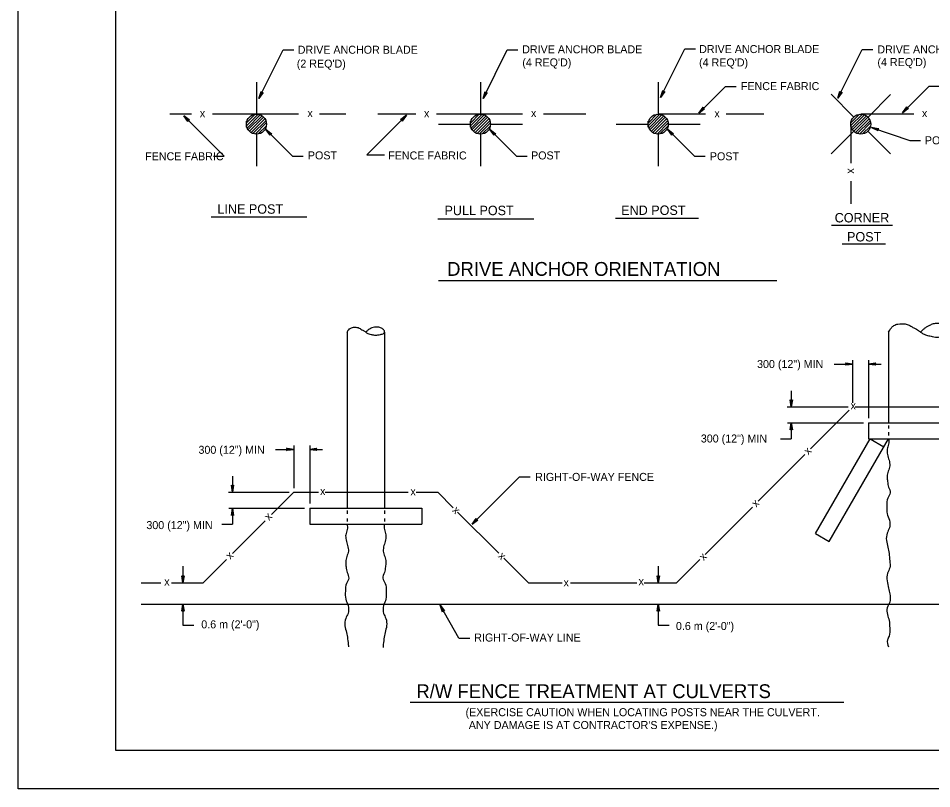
# Model space of a CAD drawing. Extents: x 13 to 918, y -903 to 879.
# Drawn here: x 13.3 to 370, y -903.1 to -602.3 of the extents above; entities that cross this region are included whole.
import ezdxf

# ---------------------------------------------------------------- set-up
doc = ezdxf.new("R2010")
doc.units = 0
for name, color, linetype in [('1', 7, 'Continuous'), ('2', 7, 'Continuous'), ('3', 7, 'Continuous'), ('PLT-BNDY', 7, 'Continuous')]:
    doc.layers.add(name, color=color, linetype=linetype)

msp = doc.modelspace()

# ---------------------------------------------------------------- linework, layer by layer
at = {"layer": '1'}
for p, q in [((80.93625, -639.7385), (72.47375, -639.7385)), ((122.69875, -639.7385), (89.157, -639.7385)), ((141.22375, -639.7385), (130.9195, -639.7385)), ((168.5155, -639.7385), (153.72375, -639.7385)), ((210.128, -639.7385), (176.607, -639.7385)), ((234.97375, -639.7385), (218.35075, -639.7385)), ((281.65775, -639.7385), (263.19525, -639.7385)), ((304.387, -639.7385), (289.73075, -639.7385)), ((363.04575, -639.7385), (342.29775, -639.7385)), ((338.3895, -643.64675), (338.3895, -658.876)), ((338.3895, -665.92175), (338.3895, -674.79675)), ((141.692, -724.81825), (141.692, -793.56825)), ((156.27525, -724.81825), (156.27525, -793.56825)), ((353.15025, -724.81825), (353.15025, -760.235)), ((331.91075, -737.27875), (339.117, -737.27875)), ((339.117, -735.79525), (339.117, -752.4265)), ((345.367, -735.79525), (345.367, -758.40575)), ((345.367, -737.27875), (350.296, -737.27875)), ((315.1795, -747.7745), (315.1795, -753.985)), ((313.617, -753.985), (337.367, -753.985)), ((313.692, -760.235), (343.346, -760.235)), ((315.1795, -760.235), (315.1795, -766.4225)), ((345.367, -760.235), (345.367, -766.485)), ((353.15025, -761.24375), (353.15025, -762.455)), ((310.96275, -766.4225), (315.1795, -766.4225)), ((353.15025, -763.828), (353.15025, -765.20075)), ((113.65225, -770.612), (120.8585, -770.612)), ((120.8585, -769.12875), (120.8585, -785.76)), ((127.1085, -769.12875), (127.1085, -791.739)), ((127.1085, -770.612), (132.03775, -770.612)), ((96.921, -781.10775), (96.921, -787.31825)), ((208.969, -781.38275), (213.18575, -781.38275)), ((95.3585, -787.31825), (119.1085, -787.31825)), ((95.4335, -793.56825), (125.08775, -793.56825)), ((96.921, -793.56825), (96.921, -799.75575)), ((127.1085, -793.56825), (127.1085, -799.81825)), ((141.692, -794.51675), (141.692, -795.72825)), ((156.27525, -794.436), (156.27525, -795.809)), ((170.8585, -793.56825), (170.8585, -799.81825)), ((141.692, -797.58575), (141.692, -798.71625)), ((156.27525, -797.58575), (156.27525, -798.797)), ((92.7045, -799.75575), (96.921, -799.75575)), ((77.542, -816.25575), (77.542, -822.735)), ((263.2335, -816.25575), (263.2335, -822.735)), ((77.542, -831.037), (77.542, -839.24125)), ((263.2335, -831.037), (263.2335, -839.24125)), ((77.542, -839.24125), (81.7585, -839.24125)), ((263.2335, -839.24125), (267.45025, -839.24125)), ((185.37525, -844.24125), (189.592, -844.24125))]:
    msp.add_line(p, q, dxfattribs=at)
msp.add_lwpolyline([(837.2505, -888.06975), (837.2505, -324.06975), (51.2505, -324.06975), (51.2505, -888.06975), (837.2505, -888.06975), (837.2505, -861.71075), (637.2505, -861.71075), (637.2505, -797.03325), (837.2505, -797.03325), (837.2505, -768.06975), (637.2505, -768.06975), (637.2505, -888.06975), (716.052, -888.06975), (716.052, -861.71075), (716.052, -888.06975), (793.052, -888.06975), (793.052, -861.71075), (793.052, -874.02725), (837.2505, -874.02725)], dxfattribs=at)
at = {"layer": '2'}
for points in [[(141.6565, -724.85775), (141.994, -724.3725), (142.3045, -723.887), (142.90025, -723.36), (143.8045, -723.0225), (145.4795, -722.99325), (146.39825, -723.264), (147.06075, -723.6975), (147.77525, -724.062), (148.27525, -724.36), (148.7065, -724.6015), (148.97725, -724.85775), (149.546, -725.237), (150.12525, -725.46625), (151.08575, -725.7515), (151.66475, -725.887), (152.367, -725.99325), (152.8795, -725.99325), (153.744, -725.9265), (154.67725, -725.7515), (155.33975, -725.6015), (156.02725, -725.264), (156.31075, -724.85775), (156.271, -724.33075), (155.85225, -723.84525), (155.35225, -723.44125), (154.78575, -723.17025), (154.01475, -722.95375), (153.09825, -722.887), (152.33975, -722.914), (151.394, -723.15775), (150.719, -723.50775), (150.08575, -723.84525), (149.5835, -724.264), (148.97725, -724.85775)], [(353.1545, -724.82025), (353.71075, -724.012), (354.244, -723.1725), (355.27325, -722.25575), (356.8045, -721.68075), (359.667, -721.64525), (361.2315, -722.10375), (362.37525, -722.82875), (363.59825, -723.47875), (364.442, -723.9725), (365.16475, -724.3975), (365.66075, -724.82025), (366.619, -725.462), (367.6085, -725.8475), (369.25225, -726.34525), (370.244, -726.5745), (371.4295, -726.76625), (372.3045, -726.76625), (373.796, -726.6475), (375.36475, -726.34525), (376.51075, -726.07875), (377.694, -725.5015), (378.169, -724.82025), (378.11075, -723.937), (377.38575, -723.09525), (376.546, -722.40575), (375.5545, -721.9475), (374.2545, -721.56825), (372.68975, -721.4515), (371.38975, -721.49525), (369.78575, -721.91), (368.60225, -722.5225), (367.5335, -723.09525), (366.692, -723.82025), (365.66075, -724.82025)]]:
    msp.add_spline(points, degree=3, dxfattribs=at)
at = {"layer": '3'}
for p, q in [((107.23625, -633.64675), (116.71325, -614.58025)), ((116.71325, -614.58025), (120.88, -614.58025)), ((194.778, -633.64675), (204.255, -614.58025)), ((204.255, -614.58025), (208.42175, -614.58025)), ((264.1015, -633.253), (273.57875, -614.1865)), ((273.57875, -614.1865), (277.74525, -614.1865)), ((333.3415, -633.5155), (342.81875, -614.449)), ((342.81875, -614.449), (346.98525, -614.449)), ((106.282, -627.2385), (106.282, -639.7385)), ((193.782, -627.2385), (193.782, -639.7385)), ((263.19525, -627.2385), (263.19525, -639.7385)), ((279.035, -639.3405), (289.4515, -628.924)), ((289.4515, -628.924), (293.61825, -628.924)), ((358.61025, -639.20925), (369.027, -628.79275)), ((369.027, -628.79275), (373.19375, -628.79275)), ((330.68525, -632.00525), (339.525, -640.84475)), ((345.13325, -640.924), (353.97275, -632.08425)), ((77.87175, -640.376), (93.6425, -656.14675)), ((102.4425, -643.12175), (105.753, -639.8115)), ((102.4675, -644.20525), (106.91125, -639.7615)), ((102.72575, -645.051), (107.728, -640.049)), ((103.08825, -645.79675), (108.45925, -640.426)), ((103.5945, -646.39475), (109.0405, -640.949)), ((104.22375, -646.874), (109.55075, -641.54675)), ((149.4155, -655.6135), (164.83625, -640.19275)), ((189.9425, -643.12175), (193.253, -639.8115)), ((189.9675, -644.20525), (194.41125, -639.7615)), ((190.22575, -645.051), (195.228, -640.049)), ((190.58825, -645.79675), (195.95925, -640.426)), ((191.0945, -646.39475), (196.5405, -640.949)), ((191.72375, -646.874), (197.05075, -641.54675)), ((259.35575, -643.12175), (262.66625, -639.8115)), ((259.38075, -644.20525), (263.8245, -639.7615)), ((259.639, -645.051), (264.64125, -640.049)), ((260.0015, -645.79675), (265.3725, -640.426)), ((260.50775, -646.39475), (265.95375, -640.949)), ((261.137, -646.874), (266.464, -641.54675)), ((338.45825, -643.12175), (341.76875, -639.8115)), ((338.48325, -644.20525), (342.927, -639.7615)), ((338.7415, -645.051), (343.74375, -640.049)), ((339.104, -645.79675), (344.475, -640.426)), ((339.61025, -646.39475), (345.05625, -640.949)), ((340.2395, -646.874), (345.5665, -641.54675)), ((102.37375, -644.81975), (102.37375, -642.474)), ((104.92375, -647.28225), (109.91325, -642.29275)), ((105.8155, -647.49475), (110.128, -643.18225)), ((106.9425, -647.476), (110.03425, -644.38425)), ((109.97375, -645.71975), (120.3905, -656.1365)), ((177.37175, -643.64675), (189.87375, -643.64675)), ((189.87375, -644.81975), (189.87375, -642.474)), ((192.42375, -647.28225), (197.41325, -642.29275)), ((193.3155, -647.49475), (197.628, -643.18225)), ((194.4425, -647.476), (197.53425, -644.38425)), ((197.47375, -645.71975), (207.8905, -656.1365)), ((197.6905, -643.64675), (210.1925, -643.64675)), ((246.785, -643.64675), (259.287, -643.64675)), ((259.287, -644.81975), (259.287, -642.474)), ((261.837, -647.28225), (266.8265, -642.29275)), ((262.72875, -647.49475), (267.04125, -643.18225)), ((263.85575, -647.476), (266.9475, -644.38425)), ((266.887, -645.71975), (277.30375, -656.1365)), ((267.10375, -643.64675), (279.60575, -643.64675)), ((340.9395, -647.28225), (345.929, -642.29275)), ((341.83125, -647.49475), (346.14375, -643.18225)), ((342.95825, -647.476), (346.05, -644.38425)), ((346.54575, -644.95525), (361.475, -650.0385)), ((106.282, -647.55525), (106.282, -660.05525)), ((193.782, -647.55525), (193.782, -660.05525)), ((263.19525, -647.55525), (263.19525, -660.05525)), ((330.79375, -655.26975), (339.63325, -646.43025)), ((345.07275, -646.44675), (353.9125, -655.2865)), ((361.475, -650.0385), (365.6415, -650.0385)), ((89.553, -656.14675), (93.6425, -656.14675)), ((120.3905, -656.1365), (124.557, -656.1365)), ((149.4155, -655.6135), (156.3405, -655.6135)), ((207.8905, -656.1365), (212.057, -656.1365)), ((277.30375, -656.1365), (281.47025, -656.1365)), ((88.52575, -679.78025), (126.007, -679.78025)), ((177.132, -680.65725), (214.61325, -680.65725)), ((246.49325, -680.39675), (278.9495, -680.39675)), ((330.8125, -683.03025), (354.69375, -683.03025)), ((335.0165, -690.43025), (351.94575, -690.43025)), ((177.34875, -704.74475), (309.50075, -704.74475)), ((322.66275, -770.439), (337.8065, -755.29525)), ((340.169, -753.985), (389.7795, -753.985)), ((345.367, -760.235), (385.367, -760.235)), ((324.5795, -803.47025), (345.9335, -766.485)), ((329.992, -806.59525), (353.15025, -766.485)), ((345.367, -766.485), (385.367, -766.485)), ((345.9335, -766.485), (351.346, -769.61)), ((302.28575, -790.81625), (320.4565, -772.64525)), ((190.48975, -799.862), (208.969, -781.38275)), ((112.12525, -796.0515), (120.8585, -787.31825)), ((120.8585, -787.31825), (130.4795, -787.31825)), ((133.15025, -787.31825), (165.5335, -787.31825)), ((168.67325, -787.31825), (177.1085, -787.31825)), ((177.1085, -787.31825), (183.16475, -793.3725)), ((127.1085, -793.56825), (170.8585, -793.56825)), ((184.8565, -795.06625), (200.93575, -811.14325)), ((281.52525, -811.5765), (300.0045, -793.0975)), ((96.869, -811.30775), (109.7335, -798.44325)), ((127.1085, -799.81825), (170.8585, -799.81825)), ((324.5795, -803.47025), (329.992, -806.59525)), ((202.9065, -813.114), (212.52525, -822.735)), ((85.442, -822.735), (94.5315, -813.64525)), ((270.367, -822.735), (279.48775, -813.614)), ((61.192, -822.735), (68.87325, -822.735)), ((73.0585, -822.735), (85.442, -822.735)), ((212.52525, -822.735), (225.644, -822.735)), ((228.896, -822.735), (254.869, -822.735)), ((257.671, -822.735), (270.367, -822.735)), ((61.192, -831.06825), (477.67525, -831.06825)), ((185.37525, -844.24125), (177.994, -831.45575)), ((166.3545, -869.26), (335.62725, -869.26))]:
    msp.add_line(p, q, dxfattribs=at)
for points in [[(108.71325, -631.424), (108.49675, -631.426), (107.23625, -633.64675), (108.71325, -631.424), (108.878, -631.353), (107.23625, -633.64675), (108.257, -631.30925), (108.13, -631.1405), (107.23625, -633.64675), (108.08, -630.95725), (108.13, -631.1405)], [(196.255, -631.424), (196.03825, -631.426), (194.778, -633.64675), (196.255, -631.424), (196.4195, -631.353), (194.778, -633.64675), (195.79875, -631.30925), (195.67175, -631.1405), (194.778, -633.64675), (195.62175, -630.95725), (195.67175, -631.1405)], [(265.57875, -631.03025), (265.362, -631.03225), (264.1015, -633.253), (265.57875, -631.03025), (265.74325, -630.95925), (264.1015, -633.253), (265.1225, -630.9155), (264.99525, -630.74675), (264.1015, -633.253), (264.94525, -630.5635), (264.99525, -630.74675)], [(334.81875, -631.29275), (334.602, -631.29475), (333.3415, -633.5155), (334.81875, -631.29275), (334.98325, -631.22175), (333.3415, -633.5155), (334.3625, -631.178), (334.23525, -631.00925), (333.3415, -633.5155), (334.18525, -630.826), (334.23525, -631.00925)], [(281.14325, -637.703), (280.937, -637.6365), (279.035, -639.3405), (281.14325, -637.703), (281.32025, -637.6885), (279.035, -639.3405), (280.7475, -637.449), (280.67875, -637.249), (279.035, -639.3405), (280.69125, -637.05925), (280.67875, -637.249)], [(360.71875, -637.57175), (360.5125, -637.50525), (358.61025, -639.20925), (360.71875, -637.57175), (360.89575, -637.55725), (358.61025, -639.20925), (360.32275, -637.31775), (360.254, -637.11775), (358.61025, -639.20925), (360.2665, -636.928), (360.254, -637.11775)], [(79.50925, -642.48425), (79.57575, -642.278), (77.87175, -640.376), (79.50925, -642.48425), (79.52375, -642.6615), (77.87175, -640.376), (79.76325, -642.0885), (79.96325, -642.01975), (77.87175, -640.376), (80.153, -642.03225), (79.96325, -642.01975)], [(162.728, -641.83025), (162.93425, -641.89675), (164.83625, -640.19275), (162.728, -641.83025), (162.55075, -641.84475), (164.83625, -640.19275), (163.12375, -642.08425), (163.1925, -642.28425), (164.83625, -640.19275), (163.18, -642.474), (163.1925, -642.28425)], [(111.61125, -647.828), (111.678, -647.62175), (109.97375, -645.71975), (111.61125, -647.828), (111.62575, -648.00525), (109.97375, -645.71975), (111.8655, -647.43225), (112.0655, -647.3635), (109.97375, -645.71975), (112.255, -647.376), (112.0655, -647.3635)], [(199.11125, -647.828), (199.178, -647.62175), (197.47375, -645.71975), (199.11125, -647.828), (199.12575, -648.00525), (197.47375, -645.71975), (199.3655, -647.43225), (199.5655, -647.3635), (197.47375, -645.71975), (199.755, -647.376), (199.5655, -647.3635)], [(268.5245, -647.828), (268.59125, -647.62175), (266.887, -645.71975), (268.5245, -647.828), (268.539, -648.00525), (266.887, -645.71975), (268.77875, -647.43225), (268.97875, -647.3635), (266.887, -645.71975), (269.16825, -647.376), (268.97875, -647.3635)], [(348.94575, -646.124), (348.9145, -645.90925), (346.54575, -644.95525), (348.94575, -646.124), (349.0375, -646.278), (346.54575, -644.95525), (348.99775, -645.65725), (349.14775, -645.50725), (346.54575, -644.95525), (349.325, -645.43425), (349.14775, -645.50725)], [(336.469, -736.94525), (336.567, -737.137), (339.117, -737.27875), (336.469, -736.94525), (336.3315, -736.83075), (339.117, -737.27875), (336.569, -737.40375), (336.47525, -737.59525), (339.117, -737.27875), (336.3315, -737.72025), (336.47525, -737.59525)], [(348.01475, -737.612), (347.917, -737.42025), (345.367, -737.27875), (348.01475, -737.612), (348.15225, -737.7265), (345.367, -737.27875), (347.91475, -737.15375), (348.0085, -736.962), (345.367, -737.27875), (348.15225, -736.837), (348.0085, -736.962)], [(315.51275, -751.337), (315.321, -751.435), (315.1795, -753.985), (315.51275, -751.337), (315.62725, -751.1995), (315.1795, -753.985), (315.0545, -751.437), (314.86275, -751.34325), (315.1795, -753.985), (314.73775, -751.1995), (314.86275, -751.34325)], [(314.846, -762.88275), (315.03775, -762.785), (315.1795, -760.235), (314.846, -762.88275), (314.7315, -763.02025), (315.1795, -760.235), (315.3045, -762.78275), (315.496, -762.8765), (315.1795, -760.235), (315.621, -763.02025), (315.496, -762.8765)], [(118.21075, -770.27875), (118.3085, -770.47025), (120.8585, -770.612), (118.21075, -770.27875), (118.07325, -770.164), (120.8585, -770.612), (118.31075, -770.737), (118.217, -770.92875), (120.8585, -770.612), (118.07325, -771.05375), (118.217, -770.92875)], [(129.7565, -770.94525), (129.6585, -770.75375), (127.1085, -770.612), (129.7565, -770.94525), (129.894, -771.06), (127.1085, -770.612), (129.6565, -770.487), (129.75025, -770.29525), (127.1085, -770.612), (129.894, -770.17025), (129.75025, -770.29525)], [(97.2545, -784.67025), (97.06275, -784.76825), (96.921, -787.31825), (97.2545, -784.67025), (97.369, -784.53275), (96.921, -787.31825), (96.796, -784.77025), (96.6045, -784.6765), (96.921, -787.31825), (96.4795, -784.53275), (96.6045, -784.6765)], [(96.58775, -796.21625), (96.7795, -796.11825), (96.921, -793.56825), (96.58775, -796.21625), (96.47325, -796.35375), (96.921, -793.56825), (97.046, -796.11625), (97.23775, -796.21), (96.921, -793.56825), (97.36275, -796.35375), (97.23775, -796.21)], [(192.59825, -798.2245), (192.392, -798.15775), (190.48975, -799.862), (192.59825, -798.2245), (192.77525, -798.21), (190.48975, -799.862), (192.20225, -797.97025), (192.1335, -797.77025), (190.48975, -799.862), (192.146, -797.58075), (192.1335, -797.77025)], [(77.87525, -820.087), (77.6835, -820.185), (77.542, -822.735), (77.87525, -820.087), (77.98975, -819.9495), (77.542, -822.735), (77.417, -820.187), (77.22525, -820.09325), (77.542, -822.735), (77.10025, -819.9495), (77.22525, -820.09325)], [(263.567, -820.087), (263.37525, -820.185), (263.2335, -822.735), (263.567, -820.087), (263.6815, -819.9495), (263.2335, -822.735), (263.1085, -820.187), (262.917, -820.09325), (263.2335, -822.735), (262.792, -819.9495), (262.917, -820.09325)], [(77.2085, -833.685), (77.40025, -833.587), (77.542, -831.037), (77.2085, -833.685), (77.094, -833.8225), (77.542, -831.037), (77.667, -833.585), (77.8585, -833.67875), (77.542, -831.037), (77.9835, -833.8225), (77.8585, -833.67875)], [(262.90025, -833.685), (263.092, -833.587), (263.2335, -831.037), (262.90025, -833.685), (262.78575, -833.8225), (263.2335, -831.037), (263.3585, -833.585), (263.55025, -833.67875), (263.2335, -831.037), (263.67525, -833.8225), (263.55025, -833.67875)], [(179.0295, -833.91625), (179.146, -833.735), (177.994, -831.45575), (179.0295, -833.91625), (178.99825, -834.09125), (177.994, -831.45575), (179.37725, -833.5995), (179.58775, -833.585), (177.994, -831.45575), (179.769, -833.64525), (179.58775, -833.585)], [(179.0295, -833.91625), (179.146, -833.735), (177.994, -831.45575), (179.0295, -833.91625), (178.99825, -834.09125), (177.994, -831.45575), (179.37725, -833.5995), (179.58775, -833.585), (177.994, -831.45575), (179.769, -833.64525), (179.58775, -833.585)]]:
    msp.add_lwpolyline(points, dxfattribs=at)
for centre in [(106.28214, -643.64679), (193.78214, -643.64679), (263.19539, -643.64679), (342.29789, -643.64679)]:
    msp.add_circle(centre, 3.9075, dxfattribs=at)
for points in [[(353.15025, -766.485), (353.192, -768.53275), (352.61275, -770.57025), (352.744, -772.6265), (353.342, -774.812), (353.62325, -777.01625), (353.044, -779.05375), (352.61275, -781.239), (352.744, -783.14525), (353.192, -785.3515), (353.771, -787.537), (352.894, -789.59325), (352.46475, -792.65575), (352.61275, -795.72025), (353.492, -798.20575), (353.492, -801.289), (352.61275, -803.3265), (352.31475, -806.11), (352.894, -808.74525), (353.342, -811.23075), (353.62325, -814.14525), (353.62325, -816.78075), (352.744, -818.96625), (352.61275, -821.8995), (353.192, -824.814), (353.62325, -827.02025), (353.62325, -830.23275), (352.61275, -832.42025), (352.744, -835.05375), (353.342, -837.389), (353.62325, -840.3245), (353.342, -843.537), (352.744, -844.99525), (353.15025, -847.735)], [(141.692, -799.81825), (141.7335, -801.86625), (141.1545, -803.90375), (141.28575, -805.96), (141.8835, -808.14525), (142.16475, -810.3495), (141.58575, -812.387), (141.1545, -814.5725), (141.28575, -816.47875), (141.7335, -818.685), (142.31275, -820.87025), (141.43575, -822.9265), (141.0065, -825.989), (141.1545, -829.05375), (142.0335, -831.539), (142.0335, -834.6225), (141.1545, -836.66), (140.8565, -839.44325), (141.43575, -842.07875), (141.8835, -844.564), (142.16475, -847.47875), (142.16475, -847.7225)], [(156.27525, -799.81825), (156.2335, -801.86625), (156.81275, -803.90375), (156.6815, -805.96), (156.0835, -808.14525), (155.80225, -810.3495), (156.3815, -812.387), (156.81275, -814.5725), (156.6815, -816.47875), (156.2335, -818.685), (155.6545, -820.87025), (156.5315, -822.9265), (156.96075, -825.989), (156.81275, -829.05375), (155.9335, -831.539), (155.9335, -834.6225), (156.81275, -836.66), (157.11075, -839.44325), (156.5315, -842.07875), (156.0835, -844.564), (155.80225, -847.47875), (155.80225, -847.96625)]]:
    msp.add_spline(points, degree=3, dxfattribs=at)
at = {"layer": 'PLT-BNDY'}
msp.add_lwpolyline([(13.2505, -309.06975), (854.2505, -309.06975), (854.2505, -903.06975), (13.2505, -903.06975)], close=True, dxfattribs=at)

# ---------------------------------------------------------------- texts
at = {"layer": '3'}
for s, height, p in [('DRIVE ANCHOR BLADE', 3.1249995, (122.40075, -616.1615)), ('DRIVE ANCHOR BLADE', 3.1249995, (210.055, -615.99275)), ('DRIVE ANCHOR BLADE', 3.1249995, (279.1725, -615.899)), ('DRIVE ANCHOR BLADE', 3.1249995, (348.76875, -616.03025)), ("(2 REQ'D)", 3.124999, (122.028, -621.58025)), ("(4 REQ'D)", 3.124999, (210.118, -621.1035)), ("(4 REQ'D)", 3.124999, (279.1525, -621.1035)), ("(4 REQ'D)", 3.124999, (348.80625, -620.98225)), ('FENCE FABRIC', 3.1249995, (295.46825, -630.3635)), ('x', 3.125, (84.15925, -640.9385)), ('x', 3.125, (126.1925, -640.901)), ('x', 3.125, (171.71325, -640.976)), ('x', 3.125, (213.4945, -640.88025)), ('x', 3.125, (366.18325, -640.91975)), ('x', 3.125, (285.135, -641.0135)), ('POST', 3.124999, (367.34375, -651.5135)), ('FENCE FABRIC', 3.1249995, (62.80925, -657.75525)), ('POST', 3.124999, (126.36125, -657.401)), ('FENCE FABRIC', 3.1249995, (157.732, -657.4365)), ('POST', 3.124999, (213.53, -657.41975)), ('POST', 3.124999, (283.35775, -657.75525)), ('LINE POST', 3.677087, (91.0175, -678.6135)), ('PULL POST', 3.677087, (179.71325, -679.176)), ('END POST', 3.677087, (248.7225, -679.0865)), ('CORNER', 3.677087, (332.11875, -682.0115)), ('POST', 3.677087, (336.925, -689.4405)), ('DRIVE ANCHOR ORIENTATION', 5.4020865, (180.732, -702.8635)), ('300 (12") MIN', 3.1249995, (301.7995, -738.84925)), ('x', 3.125, (338.3065, -755.01625)), ('300 (12") MIN', 3.1249995, (279.833, -767.92225)), ('300 (12") MIN', 3.1249995, (83.63446, -772.337)), ('RIGHT-OF-WAY FENCE', 3.1249995, (215.13575, -782.914)), ('x', 3.125, (131.121, -788.44525)), ('x', 3.125, (166.417, -788.55775)), ('300 (12") MIN', 3.1249995, (63.28696, -801.728)), ('x', 3.125, (70.26075, -823.762)), ('x', 3.125, (226.21075, -824.0975)), ('x', 3.125, (255.51075, -823.63075)), ('0.6 m (2\'-0")', 3.1249995, (84.72475, -840.462)), ('0.6 m (2\'-0")', 3.1249995, (270.11375, -841.1085)), ('RIGHT-OF-WAY LINE', 3.1249995, (191.342, -845.60575)), ('R/W FENCE TREATMENT AT CULVERTS', 5.4020865, (168.742, -867.70575)), ('(EXERCISE CAUTION WHEN LOCATING POSTS NEAR THE CULVERT.', 3.1249995, (187.93575, -874.762)), ("ANY DAMAGE IS AT CONTRACTOR'S EXPENSE.)", 3.1249995, (189.2085, -879.76825))]:
    msp.add_text(s, height=height, dxfattribs=at).set_placement(p)
for rotation, p in [(90, (339.6125, -662.96975)), (45, (321.8335, -772.95375)), (45, (301.44825, -793.412)), (45, (111.1565, -798.589)), (315, (182.5085, -794.614)), (45, (96.07525, -813.78075)), (315, (200.4085, -812.51625)), (45, (280.969, -814.2475))]:
    msp.add_text('x', height=3.125, rotation=rotation, dxfattribs=at).set_placement(p)

doc.saveas('drawing.dxf')
